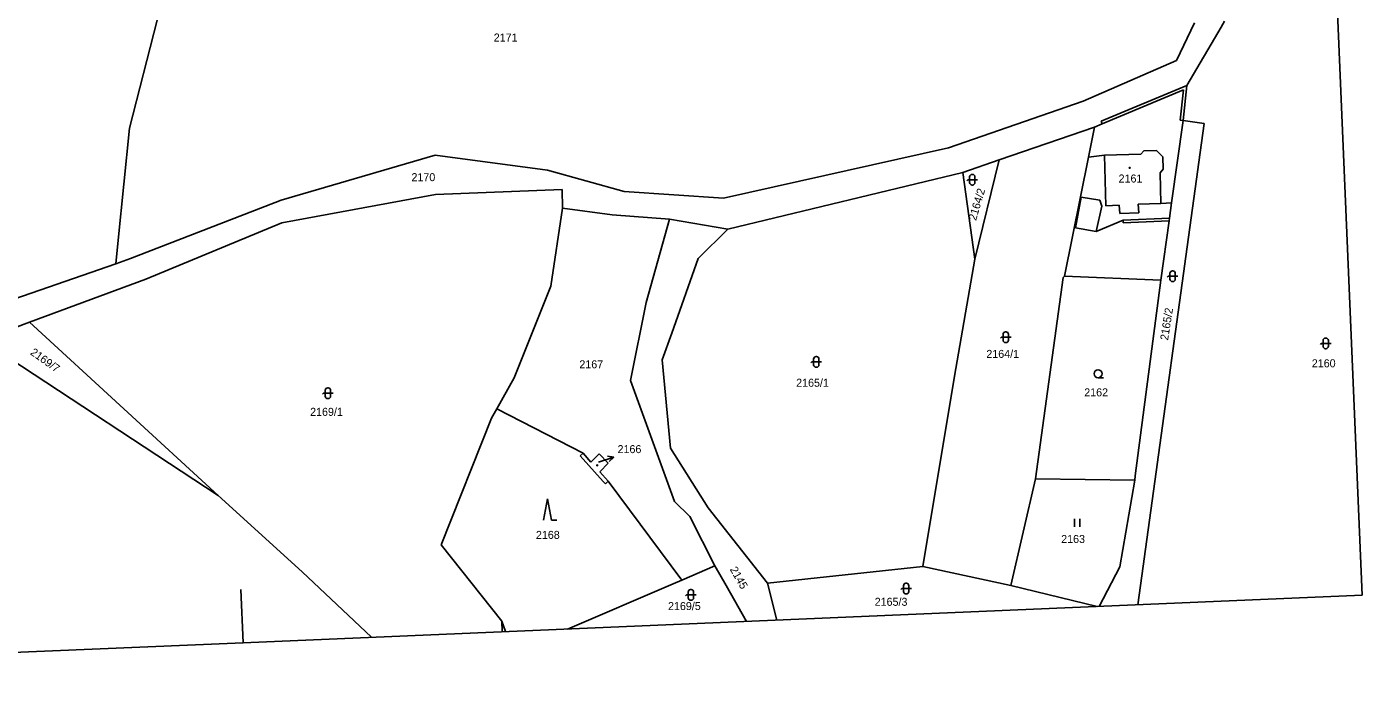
# Model space of a CAD drawing. Extents: x -806456 to -805395, y -1150847 to -1150506.
# Drawn here: x -805645 to -805394.6, y -1150820.6 to -1150696.2 of the extents above; entities that cross this region are included whole.
import ezdxf

# ---------------------------------------------------------------- set-up
doc = ezdxf.new("R2010")
doc.units = 0
for name, color, linetype in [('Default', 7, 'Continuous'), ('formát', 7, 'Continuous'), ('kn_celek - Cisla parcel pomocna', 7, 'Continuous'), ('kn_celek - Cisla pozemkovych parcel', 7, 'Continuous'), ('kn_celek - Cisla stavebnich parcel', 7, 'Continuous'), ('kn_celek - Hranice parcel', 7, 'Continuous'), ('kn_celek - Vnitrni kresby', 7, 'Continuous'), ('kn_celek - Znacky budov', 7, 'Continuous'), ('kn_celek - Znacky kultur', 7, 'Continuous')]:
    doc.layers.add(name, color=color, linetype=linetype)

# ---------------------------------------------------------------- blocks, each defined once
blk = doc.blocks.new('316')
at = {"layer": 'Default'}
for p, q in [((-8.3, 10), (-10, 8.1)), ((-5, 10), (-8.3, 10)), ((-5, 15.5), (-5, 4.5)), ((-5, 10), (5, 10)), ((0.5, 20), (-0.5, 20)), ((-0.5, 0), (0.5, 0)), ((5, 4.5), (5, 15.5)), ((10, 10), (5, 10))]:
    blk.add_line(p, q, dxfattribs=at)
for centre, start, end in [((-0.5, 15.5), 90, 180), ((-0.5, 4.5), 180, 270), ((0.5, 15.5), 0, 90), ((0.5, 4.5), 270, 0)]:
    blk.add_arc(centre, 4.5, start, end, dxfattribs=at)
blk = doc.blocks.new('304')
at = {"layer": 'Default'}
blk.add_line((-0.1, 0), (9.9, 0), dxfattribs=at)
blk.add_circle((-0.1, 7.5), 7.5, dxfattribs=at)
blk = doc.blocks.new('306')
at = {"layer": 'Default'}
for p, q in [((-5.2, 0), (-5.2, 15)), ((4.8, 0), (4.8, 15))]:
    blk.add_line(p, q, dxfattribs=at)
blk = doc.blocks.new('308')
at = {"layer": 'Default'}
for p, q in [((-7.5, 0.2), (0, 40.2)), ((0, 40.2), (7.5, 0.2)), ((7.5, 0.2), (17.5, 0.2))]:
    blk.add_line(p, q, dxfattribs=at)
blk = doc.blocks.new('402')
at = {"layer": 'Default'}
for p, q in [((-0.8, 0.8), (0.7, 0.8)), ((-0.8, 0.8), (-0.8, -0.7)), ((0.7, 0.8), (0.7, -0.7)), ((0.7, -0.7), (-0.8, -0.7))]:
    blk.add_line(p, q, dxfattribs=at)
blk = doc.blocks.new('Z61')
at = {"layer": 'Default'}
for p, q in [((0, 0), (30, 0)), ((30, 0), (19.2, 5.3)), ((30, 0), (19.2, -5.3))]:
    blk.add_line(p, q, dxfattribs=at)

msp = doc.modelspace()

# ---------------------------------------------------------------- linework, layer by layer
at = {"layer": 'formát'}
for p, q in [((-805407.21, -1150506.06), (-805394.61, -1150802.8)), ((-805604.84, -1150801.71), (-805604.42, -1150811.7)), ((-805394.61, -1150802.8), (-805604.42, -1150811.7)), ((-805604.42, -1150811.7), (-805814.23, -1150820.61))]:
    msp.add_line(p, q, dxfattribs=at)
at = {"layer": 'kn_celek - Hranice parcel'}
for p, q in [((-805620.5, -1150694.98), (-805625.71, -1150715.25)), ((-805429.45, -1150702.56), (-805426.08, -1150695.49)), ((-805421.06, -1150696.29), (-805420.42, -1150695.2)), ((-805427.5, -1150707.23), (-805421.06, -1150696.29)), ((-805446.9, -1150710.15), (-805429.45, -1150702.56)), ((-805443.58, -1150713.94), (-805427.5, -1150707.23)), ((-805428.21, -1150713.8), (-805427.5, -1150707.23)), ((-805472.19, -1150718.89), (-805446.9, -1150710.15)), ((-805625.71, -1150715.25), (-805627.8, -1150736.2)), ((-805444.78, -1150715.07), (-805462.65, -1150721.2)), ((-805445.91, -1150720.66), (-805444.78, -1150715.07)), ((-805444.78, -1150715.07), (-805443.38, -1150714.43)), ((-805443.38, -1150714.43), (-805443.58, -1150713.94)), ((-805424.25, -1150714.35), (-805436.7, -1150804.58)), ((-805430.35, -1150729.23), (-805428.21, -1150713.8)), ((-805428.21, -1150713.8), (-805424.25, -1150714.35)), ((-805568.39, -1150720.3), (-805597.28, -1150728.72)), ((-805547.32, -1150723.12), (-805568.39, -1150720.3)), ((-805514.34, -1150728.36), (-805472.19, -1150718.89)), ((-805445.91, -1150720.66), (-805450.4, -1150742.95)), ((-805547.32, -1150723.12), (-805532.97, -1150727.09)), ((-805462.65, -1150721.2), (-805469.5, -1150723.55)), ((-805462.65, -1150721.2), (-805467.24, -1150739.8)), ((-805513.56, -1150734.14), (-805469.5, -1150723.55)), ((-805469.5, -1150723.55), (-805467.24, -1150739.8)), ((-805568.35, -1150727.64), (-805597.17, -1150733)), ((-805544.61, -1150726.73), (-805568.35, -1150727.64)), ((-805544.53, -1150730.24), (-805544.61, -1150726.73)), ((-805532.97, -1150727.09), (-805514.34, -1150728.36)), ((-805625.5, -1150739.69), (-805597.28, -1150728.72)), ((-805546.71, -1150744.86), (-805544.53, -1150730.24)), ((-805544.53, -1150730.24), (-805535.21, -1150731.47)), ((-805430.35, -1150729.23), (-805430.75, -1150732.12)), ((-805597.17, -1150733), (-805622.66, -1150743.53)), ((-805535.21, -1150731.47), (-805524.47, -1150732.27)), ((-805524.47, -1150732.27), (-805528.85, -1150747.93)), ((-805524.47, -1150732.27), (-805513.56, -1150734.14)), ((-805430.82, -1150732.62), (-805432.36, -1150743.71)), ((-805430.75, -1150732.12), (-805430.82, -1150732.62)), ((-805513.56, -1150734.14), (-805519.09, -1150739.67)), ((-805628.24, -1150740.64), (-805627.8, -1150736.2)), ((-805650.48, -1150748.37), (-805628.24, -1150740.64)), ((-805628.24, -1150740.64), (-805625.5, -1150739.69)), ((-805519.09, -1150739.67), (-805524.05, -1150753.64)), ((-805467.24, -1150739.8), (-805471.05, -1150761.74)), ((-805455.86, -1150780.97), (-805450.71, -1150743.25)), ((-805450.71, -1150743.25), (-805450.4, -1150742.95)), ((-805450.4, -1150742.95), (-805432.36, -1150743.71)), ((-805644.47, -1150751.61), (-805622.66, -1150743.53)), ((-805553.57, -1150762.05), (-805546.71, -1150744.86)), ((-805437.17, -1150780.43), (-805432.36, -1150743.71)), ((-805528.85, -1150747.93), (-805531.81, -1150762.53)), ((-805653.5, -1150754.96), (-805644.47, -1150751.61)), ((-805644.47, -1150751.61), (-805609.07, -1150784.09)), ((-805653.5, -1150754.96), (-805609.07, -1150784.09)), ((-805524.05, -1150753.64), (-805525.87, -1150758.69)), ((-805525.87, -1150758.69), (-805524.26, -1150775.2)), ((-805556.85, -1150767.84), (-805553.57, -1150762.05)), ((-805531.81, -1150762.53), (-805523.52, -1150785.19)), ((-805471.05, -1150761.74), (-805477.01, -1150797.38)), ((-805557.83, -1150769.58), (-805556.85, -1150767.84)), ((-805556.85, -1150767.84), (-805540.67, -1150776.18)), ((-805567.3, -1150793.35), (-805557.83, -1150769.58)), ((-805524.26, -1150775.2), (-805517.2, -1150786.38)), ((-805540.67, -1150776.18), (-805541.2, -1150776.64)), ((-805541.2, -1150776.64), (-805536.88, -1150781.44)), ((-805539.2, -1150777.85), (-805540.67, -1150776.18)), ((-805539.2, -1150777.85), (-805537.67, -1150776.31)), ((-805537.67, -1150776.31), (-805535.97, -1150778.06)), ((-805535.97, -1150778.06), (-805537.56, -1150779.63)), ((-805537.56, -1150779.63), (-805535.96, -1150781.41)), ((-805437.27, -1150781.19), (-805437.17, -1150780.43)), ((-805536.88, -1150781.44), (-805536.48, -1150781.88)), ((-805536.48, -1150781.88), (-805535.96, -1150781.41)), ((-805535.96, -1150781.41), (-805522.19, -1150799.95)), ((-805455.86, -1150780.97), (-805460.49, -1150800.98)), ((-805455.86, -1150780.97), (-805437.27, -1150781.19)), ((-805440.04, -1150797.44), (-805437.27, -1150781.19)), ((-805609.07, -1150784.09), (-805593.36, -1150798.43)), ((-805523.52, -1150785.19), (-805520.65, -1150788.03)), ((-805520.65, -1150788.03), (-805515.95, -1150797.28)), ((-805517.2, -1150786.38), (-805506.11, -1150800.5)), ((-805555.93, -1150807.64), (-805567.3, -1150793.35)), ((-805580.33, -1150810.68), (-805593.36, -1150798.43)), ((-805522.19, -1150799.95), (-805515.95, -1150797.28)), ((-805515.95, -1150797.28), (-805513.88, -1150800.95)), ((-805477.01, -1150797.38), (-805506.11, -1150800.5)), ((-805460.49, -1150800.98), (-805477.01, -1150797.38)), ((-805443.91, -1150804.89), (-805440.04, -1150797.44)), ((-805543.59, -1150809.12), (-805523.79, -1150800.64)), ((-805523.79, -1150800.64), (-805522.19, -1150799.95)), ((-805513.88, -1150800.95), (-805510.07, -1150807.7)), ((-805506.11, -1150800.5), (-805504.37, -1150807.46)), ((-805444.31, -1150804.91), (-805460.49, -1150800.98)), ((-805555.2, -1150809.61), (-805555.93, -1150807.64)), ((-805555.93, -1150807.64), (-805555.85, -1150809.64))]:
    msp.add_line(p, q, dxfattribs=at)
at = {"layer": 'kn_celek - Vnitrni kresby'}
for p, q in [((-805428.14, -1150708.07), (-805443.38, -1150714.43)), ((-805428.75, -1150713.74), (-805428.14, -1150708.07)), ((-805428.21, -1150713.8), (-805428.75, -1150713.74)), ((-805445.91, -1150720.66), (-805442.92, -1150720.3)), ((-805442.92, -1150720.3), (-805436.12, -1150720.13)), ((-805442.7, -1150729.8), (-805442.92, -1150720.3)), ((-805436.12, -1150720.13), (-805435.57, -1150719.46)), ((-805435.57, -1150719.46), (-805433.17, -1150719.41)), ((-805433.17, -1150719.41), (-805431.97, -1150720.62)), ((-805431.97, -1150720.62), (-805431.92, -1150722.89)), ((-805431.92, -1150722.89), (-805432.48, -1150723.62)), ((-805432.48, -1150723.62), (-805432.4, -1150729.34)), ((-805448.38, -1150733.93), (-805447.3, -1150728.15)), ((-805447.3, -1150728.15), (-805443.8, -1150728.74)), ((-805443.46, -1150729.86), (-805444.47, -1150734.61)), ((-805443.8, -1150728.74), (-805443.46, -1150729.86)), ((-805442.7, -1150729.8), (-805440.16, -1150729.69)), ((-805440.06, -1150731.21), (-805440.16, -1150729.69)), ((-805432.4, -1150729.34), (-805436.59, -1150729.47)), ((-805436.59, -1150729.47), (-805436.48, -1150731.08)), ((-805432.4, -1150729.34), (-805430.35, -1150729.23)), ((-805444.47, -1150734.61), (-805439.45, -1150732.48)), ((-805436.48, -1150731.08), (-805440.06, -1150731.21)), ((-805439.45, -1150732.48), (-805430.75, -1150732.12)), ((-805439.45, -1150732.48), (-805439.43, -1150732.98)), ((-805439.43, -1150732.98), (-805430.82, -1150732.62)), ((-805444.47, -1150734.61), (-805448.38, -1150733.93))]:
    msp.add_line(p, q, dxfattribs=at)

# ---------------------------------------------------------------- block references
at = {"layer": 'kn_celek - Cisla parcel pomocna', "xscale": 0.09999999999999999, "yscale": 0.10000000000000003, "rotation": 18.434880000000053}
msp.add_blockref('Z61', (-805537.77, -1150777.84), dxfattribs=at)
at = {"layer": 'kn_celek - Znacky budov', "xscale": 0.1, "yscale": 0.10000000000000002}
for p in [(-805438.21, -1150722.66), (-805538.03, -1150778.44)]:
    msp.add_blockref('402', p, dxfattribs=at)
at = {"layer": 'kn_celek - Znacky kultur', "xscale": 0.1, "yscale": 0.10000000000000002}
for name, p in [('316', (-805467.71, -1150725.89)), ('316', (-805430.16, -1150743.99)), ('316', (-805461.44, -1150755.42)), ('316', (-805401.47, -1150756.57)), ('316', (-805496.95, -1150760.06)), ('304', (-805444.13, -1150762.02)), ('316', (-805588.5, -1150765.92)), ('308', (-805547.35, -1150788.73)), ('306', (-805448.01, -1150789.96)), ('316', (-805480.11, -1150802.55)), ('316', (-805520.47, -1150803.73))]:
    msp.add_blockref(name, p, dxfattribs=at)

# ---------------------------------------------------------------- texts
at = {"layer": 'kn_celek - Cisla parcel pomocna'}
msp.add_text('2166', height=1.5, dxfattribs=at).set_placement((-805534.21, -1150776.15))
at = {"layer": 'kn_celek - Cisla pozemkovych parcel'}
for s, p in [('2171', (-805557.42, -1150698.99)), ('2170', (-805572.84, -1150725.17)), ('2164/1', (-805465.08, -1150758.3)), ('2167', (-805541.37, -1150760.25)), ('2160', (-805404.07, -1150760.06)), ('2165/1', (-805500.73, -1150763.71)), ('2162', (-805446.73, -1150765.51)), ('2169/1', (-805591.84, -1150769.16)), ('2168', (-805549.51, -1150792.23)), ('2163', (-805451.05, -1150793)), ('2165/3', (-805486.01, -1150804.77)), ('2169/5', (-805524.75, -1150805.57))]:
    msp.add_text(s, height=1.5, dxfattribs=at).set_placement(p)
for s, rotation, p in [('2164/2', 73.4473, (-805467.02, -1150732.66)), ('2165/2', 81, (-805431.03, -1150755.09)), ('2169/7', 324.3801, (-805644.43, -1150757.55)), ('2145', 299.7, (-805513.21, -1150797.94))]:
    msp.add_text(s, height=1.5, rotation=rotation, dxfattribs=at).set_placement(p)
at = {"layer": 'kn_celek - Cisla stavebnich parcel'}
for s, height, p in [('2161', 1.5, (-805440.29, -1150725.42)), ('2166', 0.1, (-805537.77, -1150777.81))]:
    msp.add_text(s, height=height, dxfattribs=at).set_placement(p)

doc.saveas('drawing.dxf')
